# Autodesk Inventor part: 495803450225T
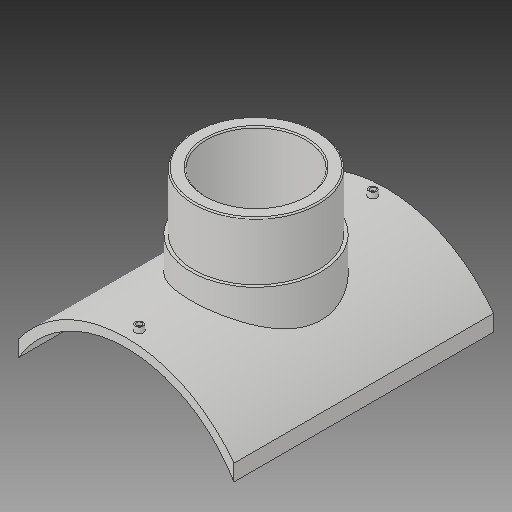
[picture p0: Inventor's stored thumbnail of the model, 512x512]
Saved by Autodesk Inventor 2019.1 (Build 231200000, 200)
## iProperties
Created: 2017-10
Part Number: 495803450225T
Material: Generic
Description: PLASSON BRANCH SADDLE 450x225
Document SubType Name: Modeling
Designer: KIM
Mass: 2754.05 g
Surface Area: 3037.44 cm^2
Volume: 2754.05 cm^3
Density: 1 g/cm^3
Appearance: Default
Author: KIM
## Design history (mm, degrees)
derived "495803.ipt"
feature "Solid1::495803.ipt"
tag "TaggingFeature1"
body "Solid1"
other parameters: "d1" = 16, "d4" = 0, "d12" = 250.6, "d13" = 14, "d14" = 211.5, "d16" = 5 deg, "d18" = 4, "d19" = 14, "d20" = 0, "d21" = 3, "d22" = 0, "d23" = 391, "d24" = 236.25, "d25" = 16, "d28" = 0, "d29" = 9.6, "d31" = 0, "d32" = 75, "d33" = 0, "d34" = 4.5, "d36" = 225, "d37" = 105, "d38" = 0, "d39" = 2.25, "d_1" = 225, "x_" = 16, "D_" = 16
